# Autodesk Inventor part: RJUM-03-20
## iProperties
Author: Malcolm
Shininess: 31.0
PropertySet Name: _Private Model Information
Created: 2001-03
Part Number: RJUM-03-20
Description: DryLin Self-adjisting Closed
Document SubType Name: Modeling
Designer: Malcolm
Control State: 0
Master: False
Checked Out: False
PropertySet Name: Design Tracking Control
Density: 0.0
Volumn: 0.0
Area: 0.0
PropertySet Name: Model Information
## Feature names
1. Revolution1
2. Extrusion1
3. Circular Pattern1
4. Extrusion2
5. Revolution2
6. Chamfer1
7. Extrusion4
8. Extrusion3
